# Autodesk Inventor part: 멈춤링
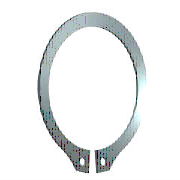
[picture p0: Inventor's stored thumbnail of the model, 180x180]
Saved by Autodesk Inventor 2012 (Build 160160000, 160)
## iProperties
IsCustomPart: 0
Created: 2009-02
Part Number: 멈춤링
Material: 강, 연강
Description: 리테이닝 링(C형)
Document SubType Name: Modeling
Standard: KS B 1336
Designer: KYOUNG IL JANG
Standards Organization: KS
Language: ko-KR
Size Designation: 22 x 1.2
Categories: <MemberInstance><Categories><Category DisplayName="샤프트 부품" InternalName="7f7aeb1f-a693-4053-b835-cee3144e0d98" Mnemonic="SHFT"><Category DisplayName="써클립" Inter
Density: 1 g/cm^3
Author: KYOUNG IL JANG
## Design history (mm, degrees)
sketch "스케치1"
  geometry: L1 (-6, 0)-(6, 0) reference; L2 (0, 20.189)-(0, -80.536) reference; L3 (-48.09, 0)-(48.09, 0) reference; L4 (-0.5, -21.488)-(-0.5, -25.588); L5 (-0.5, -6.54)-(-0.5, -13.29); L6 (-2.795, 2.7)-(3.672, 2.7); L7 (0.5, -6.54)-(0.5, -13.29); L8 (0.5, -21.488)-(0.5, -25.588); C1 r 1 at (-2, -23.437); C2 r 1 at (2, -23.437); A1 r 10.5 centre (0, -11) between (0.5, -21.488) and (-0.5, -21.488); A2 r 13.025 centre (0, -10.325) between (5.149, -22.289) and (-5.149, -22.289); A3 r 14.597 centre (0, -11) between (-2.318, -25.411) and (-0.5, -25.588); A4 r 2 centre (-2, -23.437) between (-3.97, -23.781) and (-2.318, -25.411); A5 r 2 centre (-5.94, -24.126) between (-3.97, -23.781) and (-5.149, -22.289); A6 r 2 centre (5.94, -24.126) between (5.149, -22.289) and (3.97, -23.781); A7 r 2 centre (2, -23.437) between (2.318, -25.411) and (3.97, -23.781); A8 r 14.597 centre (0, -11) between (0.5, -25.588) and (2.318, -25.411)
  constraints: 16 point on circle, 12 end point, 10 centre point, 9 symmetric about line, 5 point on line, 4 tangent, 3 coincident, 2 horizontal, 1 perpendicular, 1 vertical, 5 other
  dimensions: "d0" = 21 diameter of A1 (= ND); "d1" = 4.1 distance of L4.end L4.start (= SRB2); "d6" = 0.5 distance between parallel lines of L2 L5 (= 0.25 x SD5); "d7" = 2.7 distance between parallel lines of L6 L3 (= SRB1); "d8" = 0.675 distance of A1.centre A2.centre (= 0.25 x SRB1); "d9" = 2 radius of A4 (= SD5); "d10" = 2 radius of A5 (= SD5); "d11" = 1.5 distance from line of L4 A4.centre (= 0.75 x SD5); "d12" = 2 diameter of C1 (= SD5); "d13" = 2 diameter of C2 (= SD5); "d14" = 11 distance from line of A1.centre L1 (= 0.5 x WD)
extrude "본체" new body sketch "스케치1" distance "d2" = 1.2 (= SD); taper "d3" = 0 deg
workaxis "Work Axis1"
workplane "Work Plane1"
body "Solid1"
other parameters: "WD" = 22 (= WDMIN) [user parameter; used in 1 equation term], "SD" = 1.2 [user parameter; used in 1 equation term], "SRB1" = 2.7 [user parameter; used in 2 equation terms], "ND" = 21 [user parameter; used in 1 equation term], "SRB2" = 4.1 [user parameter; used in 1 equation term], "SD5" = 2 [user parameter; used in 6 equation terms], "d15" = 0, "d16" = 0, "d17" = 0, "d41" = 0, "d42" = 0, "WDMIN" = 22 [user parameter; used in 1 equation term], "SD3" = 20.5 [user parameter], "WDMAX" = 24 [user parameter]
